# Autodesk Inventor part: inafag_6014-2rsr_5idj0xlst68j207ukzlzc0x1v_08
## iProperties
Shininess: 64.0
Angle Display Precision: 2
Document Length Units: 11269
Document Angle Units: 11279
Document Time Units: 11290
Document Mass Units: 11283
Document Length Units Precision: 3
Document Angle Units Precision: 2
Compacted: True
Created: 2008-08
Part Number: inafag_6014-2rsr_5idj0xlst68j207ukzlzc0x1v_08
Document SubType Name: Modeling
Designer: tpomodeler
Density: 0.0
Volumn: 0.0
Area: 0.0
PropertySet Name: Model Information
Control State: 0
Master: False
Checked Out: False
Author: tpomodeler
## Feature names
1. inafag_6014-2rsr_5idj0xlst68j207ukzlzc0x1v
